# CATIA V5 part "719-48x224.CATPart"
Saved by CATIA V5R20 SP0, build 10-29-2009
Part number: 719-48x224
Definition: NONE
Nomenclature: 719-48x224
Source: Unknown
Description: 719-48x224
Bounding box of the stored display mesh (mm): x 0 to 271, y -31.5 to 31.5, z -31.5 to 31.5
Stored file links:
  C:\Users\Utente\Desktop\IO LAVORO\3D X SITO CF\X SITO\719\719-48x224.CATPart

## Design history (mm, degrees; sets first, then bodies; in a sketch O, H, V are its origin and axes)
Body1 "719-48x224" (main body)
  Solid1: solid without history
